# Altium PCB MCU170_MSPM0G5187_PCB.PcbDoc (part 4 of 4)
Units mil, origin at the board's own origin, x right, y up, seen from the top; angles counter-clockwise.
Board outline 2300 x 4450 mil, 4 copper layers (Top Layer, VCC Layer, GND Layer, Bottom Layer), stack 62.4 mil thick; 276 components, 190 nets, 913 pads, 323 vias.
Unrouted connection lines stored in the file: 4.
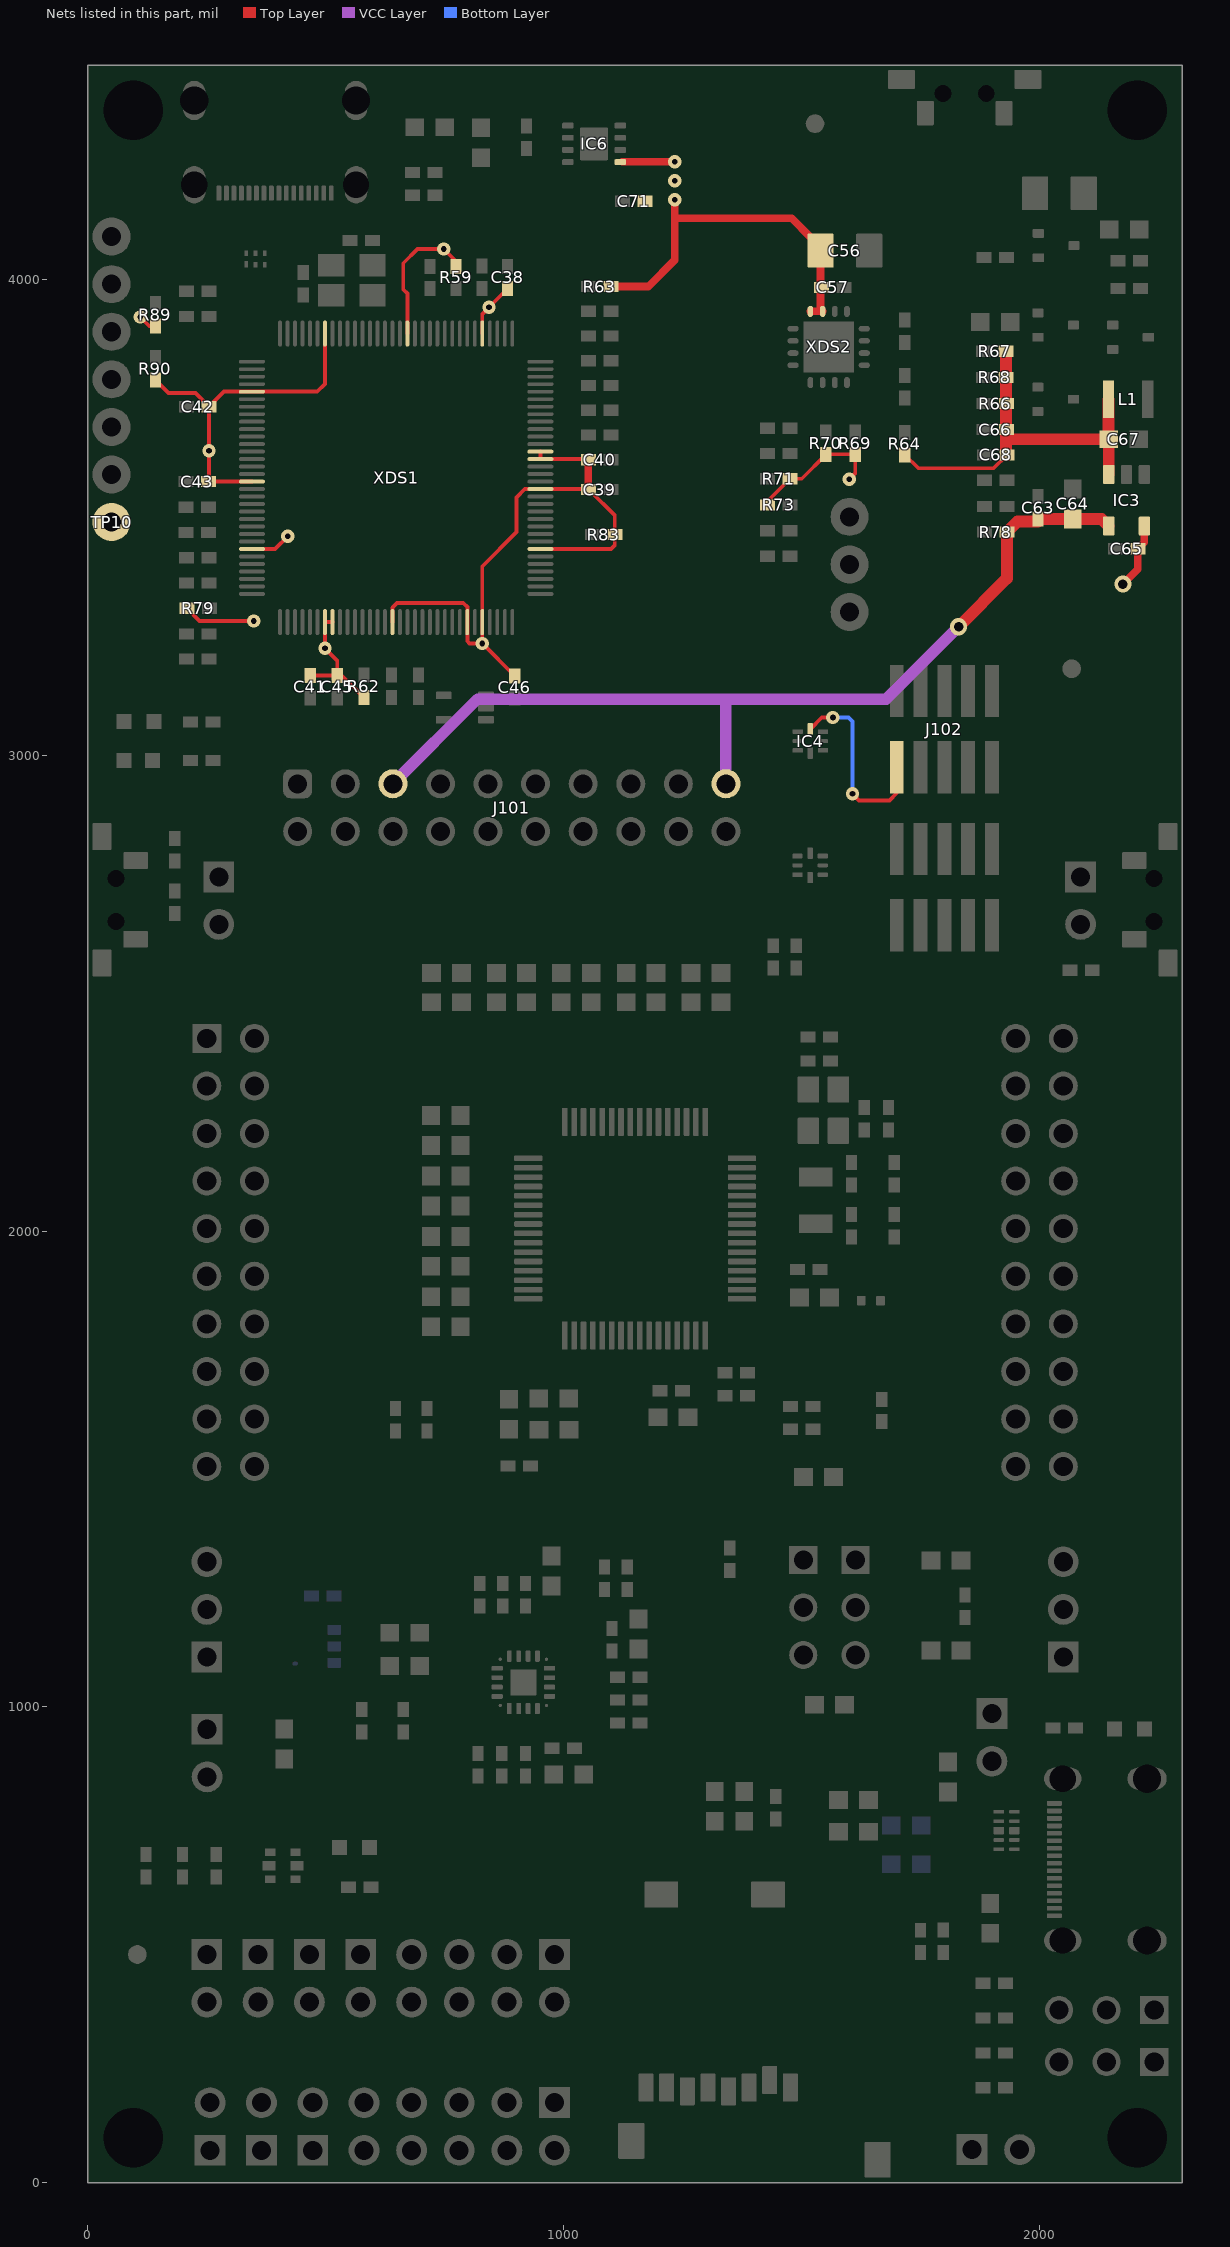
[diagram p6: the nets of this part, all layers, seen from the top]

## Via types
v1: diameter 28, hole 12, Top Layer to Bottom Layer, 291 vias
v2: diameter 19.68, hole 7.87, Top Layer to Bottom Layer, 9 vias
v3: diameter 36, hole 20, Top Layer to Bottom Layer, 8 vias
v4: diameter 24, hole 12, Top Layer to Bottom Layer, 4 vias
v5: diameter 24, hole 12, Top Layer to Bottom Layer, tented both sides, 4 vias
v6: diameter 19.68, hole 7.87, Top Layer to Bottom Layer, tented both sides, 4 vias
v7: diameter 28, hole 12, Top Layer to Bottom Layer, tented both sides, 2 vias
v8: diameter 39.37, hole 39.37, Top Layer to Bottom Layer, 1 vias

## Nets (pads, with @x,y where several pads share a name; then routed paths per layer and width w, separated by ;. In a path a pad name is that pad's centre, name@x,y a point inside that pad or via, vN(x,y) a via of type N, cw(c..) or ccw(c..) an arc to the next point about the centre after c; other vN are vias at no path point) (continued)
XDS_VCC: C38.1 C39.1 C40.1 C41.1 C42.1 C43.1 C45.1 C46.1 C56.1 C57.1 C65.1 C71.1 IC3.5 IC4.8 IC6.1 J102.1 R59.2 R62.2 R63.2 R69.2 R70.2 R71.2 R73.2 R79.2 R83.2 R89.1 R90.1 TP10.1 XDS1.7 XDS1.8 XDS1.16 XDS1.26 XDS1.28 XDS1.39 XDS1.47 XDS1.51 XDS1.52 XDS1.69 XDS1.79 XDS1.90 XDS1.101 XDS1.113 XDS1.122 XDS2.15 XDS2.16 | length 4812.5
  Top Layer w8: v1(110.33,3921) 129.2,3902.13 R89.1@142,3902.13 ; R90.1@142,3788.76 169.76,3761 226.23,3761 C42.1@254.62,3732.61 ; R79.2@208,3309 235,3282 v1(349,3282) ; C43.1@253.62,3575 C43.1@253.75,3575.13 ; XDS1.122@344.85,3433.39 393.39,3433.39 v1(420,3460) ; XDS1.113@344.85,3575.13 C43.1@253.75,3575.13 ; C41.1@467.5,3167.62 C45.1@524,3167.62 ; XDS1.90@498.39,3886.15 498.39,3780.3 482.19,3764.1 XDS1.101@344.85,3764.1 286.12,3764.1 C42.1@254.62,3732.61 ; XDS1.8@514.14,3279.85 XDS1.7@498.39,3279.85 v1(498.39,3224.61) 524,3199 C45.1@524,3167.62 ; R62.2@580.4,3121.01 533.79,3167.62 C45.1@524,3167.62 ; XDS1.16@640.13,3279.85 640.13,3310.13 650,3320 789,3320 797.61,3311.39 XDS1.26@797.61,3279.85 797.61,3239.39 802.1,3234.9 v1(829.1,3234.9) ; XDS1.79@671.62,3886.15 671.62,3970.06 663,3978.68 663,4034.06 692.94,4064 v1(748,4064) 774,4038 R59.2@774,4027.62 ; XDS1.69@829.1,3886.15 829.1,3927.48 v1(843,3941.38) C38.1@882,3980.38 ; C46.1@897,3167 v1(829.1,3234.9) ; XDS1.39@951.15,3433.39 1099.47,3433.39 1107.55,3441.48 R83.2@1107.55,3463.63 1107.55,3503.73 C39.1@1055.98,3555.31 ; XDS1.52@951.15,3638.12 XDS1.51@951.15,3622.37 C40.1@1051.04,3622.37 ; C39.1@1051.04,3559.38 XDS1.47@951.15,3559.38 918.38,3559.38 901,3542 901,3469.21 829.1,3397.31 XDS1.28@829.1,3279.85 v1(829.1,3234.9) ; C39.1@1052.04,3563 C39.1@1055.98,3563 ; R73.2@1428.38,3526 1428.38,3533.76 R71.2@1475.62,3581 1500.27,3581 R70.2@1551,3631.73 1551.65,3632.38 R69.2@1613,3632.38 1613,3593 v1(1600,3580) ; IC4.8@1518.56,3055.47 1542.24,3079.15 v1(1565.85,3079.15) ; v1(1607,2919) 1621,2905 1684.72,2905 1700,2920.28 J102.1@1700,2974.88 ; C43.1@253.75,3575.13 254.62,3576 v1(254.62,3640) C42.1@254.62,3732.61
  Top Layer w16: C39.1@1052.04,3563 C40.1@1052.04,3621 ; R63.2@1099.29,3985 1177.45,3985 1233.24,4040.79 1233.24,4122.95 v1(1233.24,4167.54) ; IC6.1@1122.76,4247.54 v1(1233.24,4247.54) ; 1233.24,4128.48 1479.37,4128.48 1519.84,4088.01 1520.28,4088.01 1539.84,4068.45 1539.84,3983 1539.84,3937.17 XDS2.15@1544.2,3932.8 XDS2.16@1518.61,3932.8 ; v3(2175.23,3359.67) 2206.62,3391.06 C65.1@2206.62,3434 2220.4,3447.78 IC3.5@2220.4,3481.73
  Bottom Layer w8: v1(1565.85,3079.15) 1598.85,3079.15 1607,3071 v1(1607,2919)
  other v1: 1233.24,4207.54
XDS_VCCOUT: C66.1 C67.2 C68.1 IC3.3 L1.2 R64.2 R66.2 R67.2 R68.2 | length 830.6
  Top Layer w8: R64.2@1717,3631.38 1745.38,3603 1903.62,3603 C68.1@1931.62,3631
  Top Layer w25: R67.2@1930,3849.2 R68.2@1930,3794 1930,3663.85 ; C68.1@1931.62,3631 1930,3632.62 1930,3663.85 ; L1.2@2145.06,3748 2145.06,3664.44 C67.2@2145.5,3664 ; IC3.3@2145.6,3590 2145.5,3590.09 C67.2@2145.5,3664 ; 1930,3663.85 1930.15,3664 C67.2@2145.5,3664
XDS_VCCTARGET: C63.1 C64.1 IC3.4 J101.5 J101.19 R78.2 | length 1979.4
  Top Layer w25: v3(1830,3270) 1931.62,3371.62 R78.2@1931.62,3469 1953.44,3490.81 1997,3490.81 C63.1@1997,3496.38 2130.95,3496.38 IC3.4@2145.6,3481.73
  VCC Layer w24: J101.5@641.04,2940 819.04,3118 1341.04,3118 ; J101.19@1341.04,2940 1341.04,3118 ; v3(1830,3270) 1678,3118 1436.65,3118 1341.04,3118
pads on no net: FID1.1 FID2.1 FID3.1 IC2.2 IC2.4 IC2.5 IC5.1 IC5.2 IC6.2 IC6.3 IC6.6 IC6.7 J16.1 J16.8 J103.6 J103.8 J104.A8 J104.B8 J105.A8 J105.B8 MH1.1 MH2.1 MH3.1 MH4.1 S1. S2. S3. SH-J1.0 SH-J2.0 SH-J3.0 SH-J4.0 SH-J5.0 SH-J6.0 SH-J7.0 SH-J8.0 SH-J9.0 SH-J10.0 SH-J11.0 SH-J12.0 SH-J13.0 SH-J14.0 SH-J15.0 SH-J16.0 SH-J17.0 SH-J18.0 SH-J19.0 SH-J20.0 SH-J21.0 SH-J22.0 SH-J23.0 U3.1 U3.3 U4.3@1947.34,740.03 U4.6 U4.7 U4.8@1914.47,740.03 XDS1.2 XDS1.12 XDS1.13 XDS1.14 XDS1.15 XDS1.18 XDS1.19 XDS1.20 XDS1.21 XDS1.22 XDS1.23 XDS1.24 XDS1.25 XDS1.29 XDS1.30 XDS1.31 XDS1.32 XDS1.41 XDS1.43 XDS1.44 XDS1.45 XDS1.46 XDS1.53 XDS1.54 XDS1.56 XDS1.57 XDS1.65 XDS1.67 XDS1.71 XDS1.72 XDS1.73 XDS1.74 XDS1.75 XDS1.76 XDS1.81 XDS1.82 XDS1.83 XDS1.84 XDS1.85 XDS1.86 XDS1.91 XDS1.92 XDS1.102 XDS1.103 XDS1.104 XDS1.105 XDS1.106 XDS1.107 XDS1.108 XDS1.109 XDS1.110 XDS1.111 XDS1.112 XDS1.116 XDS1.117 XDS1.118 XDS1.119 XDS1.121 XDS1.123 XDS1.124 XDS1.125 XDS1.126
copper on no net:
  other v8: 435.76,1127.17

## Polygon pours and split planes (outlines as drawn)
MSP_VBUS on Top Layer "TOP_LAYER_MSP_VBUS_P089" (solid, pour order 89): 1991.58,751.04 1991.58,796.99 1900,796.99 1900,751.04
XDS_VCC on Top Layer "TOP_LAYER_XDS_VCC_P082" (solid, pour order 82): 1152.72,4270.71 1263.3,4270.71 1263.3,4105.54 1152.72,4105.54
MSP_VBUS on Top Layer "TOP_LAYER_MSP_VBUS_P088" (solid, pour order 88): 2197.07,587.34 2197.08,770.54 1860.95,770.54 1860.95,587.34
+5V on Top Layer "TOP_LAYER_+5V_P099" (solid, pour order 99): 2082.59,1072.26 2082.59,1137.38 1815.52,1137.38 1815.52,1072.26
+5V on Top Layer "TOP_LAYER_+5V_P098" (solid, pour order 98): 1939.59,951.48 1939.6,1137.38 1815.52,1137.38 1815.52,951.48
SD_VDD on Top Layer "TOP_LAYER_SD_VDD_P097" (solid, remove dead copper, pour order 97): 1290.32,793.21 1498.89,793.21 1498.89,893.53 1290.32,893.53
VBUS1 on Top Layer "TOP_LAYER_VBUS1_P081" (solid, pour order 81): 303.1,4048.74 484.25,4048.73 484.25,4367.56 303.1,4367.56
3V3 on Top Layer "TOP_LAYER_3V3_P091" (solid, remove dead copper, pour order 91): 1446.37,1931.2 1446.37,1770.25 1520.73,1770.25 1520.73,1931.2
29_VUSB on Top Layer "TOP_LAYER_29_VUSB_P092" (solid, remove dead copper, pour order 92): 1233.85,1736.75 1233.85,1512.97 1299.54,1512.97 1299.54,1736.75
GND on Top Layer "TOP_LAYER_GND_P100" (solid, remove dead copper, pour order 100): 0,2885.36 2306,2885.36 2306,0 0,0
XDS_GND on Top Layer "TOP_LAYER_XDS_GND_P083" (solid, remove dead copper, pour order 83): -6,4456 2306,4456 2306,2890 -6,2890
GND on GND Layer "GND_LAYER_GND_P096" (solid, remove dead copper, pour order 96): 0,2889.64 2298.04,2889.64 2298.04,0 0,0
XDS_GND on GND Layer "GND_LAYER_XDS_GND_P084" (solid, remove dead copper, pour order 84): -6,4456 2306,4456 2306,2890 -6,2890
VBUS1 on VCC Layer "VCC_LAYER_VBUS1_P086" (solid, remove dead copper, pour order 86): 280,4367.56 280,4048.48 515,4048.48 515,4367.56
3V3 on VCC Layer "VCC_LAYER_3V3_P095" (solid, remove dead copper, pour order 95): 0,2890 2300,2890 2300,0 0,0
MSP_VBUS on VCC Layer "VCC_LAYER_MSP_VBUS_P093" (solid, pour order 93): 2188.52,589.52 2188.53,772.73 1807.97,772.73 1807.97,589.52
XDS_VCC on VCC Layer "GND_LAYER_GND_P-001" (solid, remove dead copper, pour order 87): -6,4450 2300,4450 2300,2890 -6,2890
GND on Bottom Layer "BOTTOM_LAYER_GND_P090" (solid, remove dead copper, pour order 90): 0,2885.36 2301.96,2885.36 2301.96,0 0,0
XDS_GND on Bottom Layer "BOTTOM_LAYER_XDS_GND_P085" (solid, remove dead copper, pour order 85): -6,4456 2306,4456 2306,2890 -6,2890

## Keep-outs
Keep-Out Layer:
  text ".Layer_Name" at 527,-1268.49 h30

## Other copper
Top Layer:
  pour cut-out: 2054.2,625.96 2054.2,607.85 1973.55,607.85 1973.55,625.96
  pour cut-out: 1602.77,1834.01 1602.77,1873.14 1643.84,1873.14 1643.84,1834.01
  pour cut-out: 1643.84,1850.09 1621.72,1872.21 1677.36,1927.85 1699.48,1905.73
  pour cut-out: 1006.62,2418.91 1006.62,2448.7 1062.16,2448.7 1062.16,2418.91
  pour cut-out: 1930.57,2571.96 1930.57,2742.89 1721.74,2742.9 1721.74,2571.96
  pour cut-out: 2062.89,749.86 2062.89,733.86 1967.74,733.86 1967.74,749.86
  pour cut-out: 1322.46,1988.03 1322.46,2034.53 1358.33,2034.53 1358.33,1988.03
  pour cut-out: 1863.59,284.39 1863.59,296.77 1896.91,296.77 1896.91,284.39
  pour cut-out: 1571.6,807.81 1571.6,798.63 1448.2,798.63 1448.2,807.81
  pour cut-out: 92.29,3757.01 92.29,3763.56 162.5,3763.56 162.5,3757.01
  pour cut-out: 1632.81,2175.68 1669.62,2175.68 1669.62,2112.18 1632.81,2112.18
  pour cut-out: 1973.93,696.26 1973.93,680.26 1860.95,680.26 1860.95,696.26
  pour cut-out: 807.59,1321.24 797.5,1331.32 823.17,1356.99 833.26,1346.91
  pour cut-out: 1210,1348.42 1220.08,1358.51 1245.75,1332.84 1235.67,1322.75
  pour cut-out: 1245.75,1186.35 1229.75,1186.35 1229.75,1358.51 1245.75,1358.51
  pour cut-out: 1245.75,1358.51 1245.75,1342.51 802.42,1342.51 802.42,1358.51
  pour cut-out: 812.09,1236.12 796.09,1236.12 796.09,1358.51 812.09,1358.51
  pour cut-out: 797.51,1628.18 797.51,1640.52 926.52,1640.52 926.52,1628.18
  pour cut-out: 964.69,1543.04 964.69,1613.16 981.89,1613.16 981.89,1543.04
  pour cut-out: 795.21,1534.07 795.21,1549.53 959.27,1549.53 959.27,1534.07
  pour cut-out: 391.98,4062.32 391.98,4068.88 485.16,4068.88 485.16,4062.32
  pour cut-out: 1949.06,551.33 1949.06,527.97 1860.93,527.97 1860.93,551.33
  pour cut-out: 1865.67,366.48 1851.64,366.48 1851.64,551.28 1865.67,551.28
  pour cut-out: 991.75,1253.23 974.23,1253.23 974.23,1237.09 991.75,1237.09
  pour cut-out: 1491.99,2182.5 1491.99,2254.64 1545.49,2254.64 1545.49,2182.5
  pour cut-out: 1481.99,2435.83 1481.99,2457.64 1583.71,2457.64 1583.71,2435.83
  pour cut-out: 1218.19,1601.19 1232.22,1601.19 1232.22,1572.9 1218.19,1572.9
  pour cut-out: 1217.87,1647.79 1231.9,1647.79 1231.9,1625.57 1217.87,1625.57
  pour cut-out: 1136.51,1498.94 1136.51,1512.97 1276.11,1512.97 1276.11,1498.94
  pour cut-out: 1523.91,1770.53 1523.91,1909.48 1543.44,1909.48 1543.44,1770.53
  pour cut-out: 1667.02,1873.27 1667.02,1963.17 1705.9,1963.17 1705.9,1873.27
  pour cut-out: 1667.02,2039.54 1667.02,2076.34 1722.64,2076.34 1722.64,2039.54
  pour cut-out: 1673.19,2291.56 1654.79,2291.56 1654.79,2420.43 1673.19,2420.43
  pour cut-out: 1592.73,2380.21 1592.73,2420.43 1655.03,2420.43 1655.03,2380.21
  pour cut-out: 795.21,1534.07 795.21,1630.38 809.64,1630.38 809.64,1534.07
  pour cut-out: 1230.77,1732.08 1230.77,1768.89 1286.39,1768.89 1286.39,1732.08
  pour cut-out: 1206.56,1733.67 1206.72,1733.51 1226.43,1733.51 1226.43,1694.71 1222.91,1691.19 1198.86,1691.19
  pour cut-out: 1490.09,2047.17 1490.09,2083.98 1581.43,2083.98 1581.43,2047.17
  pour cut-out: 1930.57,2880.51 1930.57,3069 1727.58,3069 1727.58,2880.51
  text ".Layer_Name" at 527,-1268.49 h30
VCC Layer:
  text ".Layer_Name" at 527,-1268.49 h30
GND Layer:
  text ".Layer_Name" at 527,-1268.49 h30
Bottom Layer:
  pour cut-out: 548.85,1260.77 485.35,1260.77 485.35,1325.51 548.85,1325.51
  pour cut-out: 617.43,1088.43 558.39,1088.43 558.39,1119.74 617.43,1119.74
  pour cut-out: 507.61,1072.12 485.54,1050.05 473.87,1061.72 495.94,1083.79
  pour cut-out: 503.94,1168.75 503.94,1072.12 487.43,1072.12 487.43,1168.75
  pour cut-out: 485.54,1050.05 357.8,1050.05 357.8,1066.05 485.54,1066.05
  pour cut-out: 1552.81,2319.53 1552.81,2421.67 1655.71,2421.67 1655.71,2348.61 1626.63,2319.53
  text ".Layer_Name" at 527,-1268.49 h30

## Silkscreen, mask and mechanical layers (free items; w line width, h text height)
Top Overlay:
  drawing of 1922 lines, arcs and shapes, not listed
  text "MSP NRST" at 1617.89,4235.03 h40
  text "USB1" at 385.12,4107.63 h30
  text "Rev. A" at 2264.13,3068.42 h50 r90
  text "XDS110-ET Debug Probe" at 426.78,3015.68 h30
  text "Rev1.6" at 1158.45,3015.68 h30
  text "XDS110 Out" at 1650.72,2923 h30 r90
  text "LP-MSPM0G5187" at 2205.15,2920.28 h65 r90
  text "BSL" at 1261.52,2627.58 h40 r90
  text "NRST" at 970.08,2608.15 h40 r90
  text "VUSB" at 1363.44,2608.15 h40 r90
  text "XDS110 In" at 1647,2595.5 h30 r90
  text "SWDIO" at 1064.21,2592.15 h40 r90
  text "SWCLK" at 1159.62,2592.15 h40 r90
  text "RXD<<" at 765.08,2590.15 h40 r90
  text "TXD>>" at 865.08,2590.15 h40 r90
  text "(PA18)" at 212.43,2538.56 h40
  text "(PA7)" at 1860.65,2523.09 h40
  text "PB4" at 1754,2385 h60
  text "MSPM0G5187" at 994.02,2291.67 h55
  text "PA25" at 50,2285 h60
  text "PB5" at 1754,2285 h60
  text "PB26" at 2152,2285 h60
  text "PB3" at 50,2185 h60
  text "PB14" at 460,2185 h60
  text "PB0" at 1754,2185 h60
  text "PB24" at 2152,2185 h60
  text "PB2" at 50,2085 h60
  text "PB15" at 460,2085 h60
  text "PB1" at 1754,2085 h60
  text "PB23" at 2152,2085 h60
  text "PB21" at 50,1985 h60
  text "PB16" at 460,1985 h60
  text "PA28" at 1754,1985 h60
  text "NRST" at 2152,1985 h60
  text "PB22" at 50,1885 h60
  text "PA16" at 460,1885 h60
  text "PA31" at 1754,1885 h60
  text "PB17" at 2152,1885 h60
  text "PB18" at 50,1785 h60
  text "PA15" at 460,1785 h60
  text "PA10" at 1754,1785 h60
  text "PB19" at 2152,1785 h60
  text "PB25" at 50,1685 h60
  text "PA12" at 460,1685 h60
  text "PA11" at 1754,1685 h60
  text "PA30" at 2152,1685 h60
  text "PA9" at 50,1585 h60
  text "PA13" at 460,1585 h60
  text "PA0" at 1754,1585 h60
  text "PA29" at 2152,1585 h60
  text "PA8" at 50,1485 h60
  text "PA14" at 460,1485 h60
  text "PA1" at 1754,1485 h60
  text "PA22" at 2152,1485 h60
  text "PCM1809" at 1013.29,1331.99 h60
  text "3V" at 1381.47,1300.72 h60
  text "3V" at 1671.76,1300.46 h60
  text "Microphone" at 441.8,1275 h60
  text "5V" at 1376.79,1080.14 h60
  text "5V" at 1671.72,1077.85 h60
  text "PA0" at 1387.36,1004.06 h60
  text "PA1" at 1640.23,1003.4 h60
  text "5V" at 1763.28,968.15 h60
  text "VM" at 121.82,941.97 h50
  text "VBUS" at 1974.04,882.55 h60
  text "3V3" at 109.67,836.79 h50
  text "PB12" at 630.33,584.83 h48
  text "PB10" at 740.05,585.36 h48
  text "PB8" at 850,585.36 h48
  text "PB6" at 945.06,585.36 h48
  text "USB2" at 2001.8,579.54 h30 r90
  text "PB13" at 630.33,543.16 h48
  text "PB11" at 743.14,542.62 h48
  text "PB9" at 850,543.16 h48
  text "PB7" at 945.06,542.62 h48
  text "DEVICE" at 2137.8,449.11 h40
  text "J25" at 1967.29,432.47 h30
  text "24" at 2071.05,432.08 h30
  text "/" at 2051.96,428.02 h60
  text "PB13" at 129,287.84 h48
  text "PA0" at 488,287.84 h48
  text "PA17" at 248.71,287.31 h48
  text "PA24" at 368.42,287.31 h48
  text "B20" at 644.42,281.13 h50
  text "A6" at 754.29,281.13 h50
  text "A4" at 854.48,280.58 h50
  text "A27" at 944.83,280.58 h50
  text "A2" at 579,270 h48
  text "A21" at 644.42,234.72 h50
  text "A5" at 753.19,235.28 h50
  text "A3" at 854.04,235.28 h50
  text "A26" at 944.83,235.28 h50
  text "GND" at 209.53,230 h48
  text "3V3" at 333,230 h48
  text "5V" at 448.26,230 h48
  text "A23" at 554.8,227.5 h48
  text "CC" at 1975.82,164.24 h30
  text "HOST" at 2045.96,143.35 h40
  text "PLUGIN_DETECT" at 1726.93,126.7 h40
  text "PB21" at 2021.92,18.18 h60
  text ".Layer_Name" at 527,-1268.49 h30
Bottom Overlay:
  drawing of 23340 lines, arcs and shapes, not listed
  text ".Layer_Name" at 976.62,5050.85 h60
  text "PB4" at 1860,2384.3 h60
  text "PA25" at 145.94,2285.07 h60
  text "PB5" at 1860,2284.3 h60
  text "PB26" at 2278,2284.3 h60
  text "PB3" at 145.94,2185.07 h60
  text "PB14" at 580,2185.07 h60
  text "PB0" at 1860,2184.3 h60
  text "PB24" at 2278,2184.3 h60
  text "PB2" at 145.94,2085.07 h60
  text "PB15" at 580,2085.07 h60
  text "PB1" at 1860,2084.3 h60
  text "PB23" at 2278,2084.3 h60
  text "PB21" at 145.94,1985 h60
  text "PB16" at 580,1985.07 h60
  text "PA28" at 1860,1984.3 h60
  text "NRST" at 2278,1984.3 h60
  text "PB22" at 145.94,1885 h60
  text "PA16" at 580,1885.07 h60
  text "PA31" at 1860,1884.3 h60
  text "PB17" at 2278,1884.3 h60
  text "PB18" at 145.94,1785.07 h60
  text "PA15" at 580,1785.07 h60
  text "PA10" at 1860,1784.3 h60
  text "PB19" at 2278,1784.3 h60
  text "PB25" at 145.94,1685.07 h60
  text "PA12" at 580,1685.07 h60
  text "PA11" at 1860,1684.3 h60
  text "PA30" at 2278,1684.3 h60
  text "PA9" at 145.94,1585.07 h60
  text "PA13" at 580,1585.07 h60
  text "PA0" at 1860,1584.3 h60
  text "PA29" at 2278,1584.3 h60
  text "PA8" at 145.94,1485.07 h60
  text "PA14" at 580,1485.07 h60
  text "PA1" at 1860,1484.3 h60
  text "PA22" at 2278,1484.3 h60
  text "DP" at 1707,799.21 h30
  text "PULL" at 2277,626 h60
  text "DM" at 1707,586.99 h30
  text "PULLUP" at 2082.59,579 h60
  text "DOWN" at 2277,579 h60
  text "CC2" at 1971.43,342.73 h60
  text "CC1" at 1972.43,234.73 h60
  text ".Layer_Name" at 527,-1268.49 h30
Top Paste:
  text ".Layer_Name" at 527,-1268.49 h30
Bottom Paste:
  text ".Layer_Name" at 527,-1268.49 h30
Top Solder:
  text ".Layer_Name" at 527,-1268.49 h30
  text ".Layer_Name" at 527,-1268.49 h30
Bottom Solder:
  text ".Layer_Name" at 527,-1268.49 h30
Drill Guide:
  text ".Layer_Name" at 527,-1268.49 h30
M1 Board Outline:
  the board outline again, w1
  text ".Layer_Name" at 527,-1268.49 h30
M2 Board Dimensions:
  rectangle: 75,-810 450,-685
  rectangle: -50,-685 75,-560
  lines w7: -50,-685 950,-685 ; 75,-810 75,-560 ; 200,-810 200,-560 ; 450,-810 450,-560 ; 700,-810 700,-560 ; -50,-810 -50,-560 950,-560 950,-810 -50,-810
  text ".Layer_Name" at 527,-1268.49 h30
M3 3D STEP Top:
  text ".Layer_Name" at 527,-1268.49 h30
M4 3D STEP Bottom:
  text ".Layer_Name" at 527,-1268.49 h30
M5 Assembly Top:
  circle w6: c1382.04,2127 r5.83
  lines w10: -342,-1340.17 6258,-1340.17 ; -342,-1136.83 6260,-1136.83 ; -342,-933.5 -342,-1543.5 3663,-1543.5 6260,-1543.5 6260,-933.5 -341.5,-933.5 -341.5,-1543.5 1234,-1543.5 ; 2123,-1543.5 2123,-933.5 ; 3390,-1136.83 3390,-933.5 ; 4230,-1136.83 4230,-933.5 ; 4852,-1550 4852,-1347.17
  text "COMPONENTS MARKED 'DNP' SHOULD NOT BE POPULATED." at 1103.5,-728.5 h30
  text "ASSEMBLY VARIANT:" at 1103,-844 h30
  text ".VariantName" at 2139,-844 h30
  text "PCB VIEWED FROM TOP SIDE" at -278.5,-1065.67 h30
  text "BOARD #:" at 2198,-1065.67 h30
  text ".PRJ_Number" at 2743.5,-1065.67 h30
  text "REV:" at 3588,-1065.67 h30
  text ".PCB_Rev" at 3879.5,-1065.67 h30
  text "SVN REV:" at 4426,-1065.67 h30
  text ".VersionControl_RevNumber" at 4932,-1065.67 h30
  text "TID #:" at 2198,-1269 h30
  text ".TID" at 2743.5,-1269 h30
  text "PLOT NAME =" at -278.5,-1474.34 h30
  text ".plot_File_Name" at 527,-1474.34 h30
  text "GENERATED    :" at 2200,-1474.34 h30
  text ".Print_Date" at 3069.5,-1474.34 h30
  text ".Print_Time" at 3798.5,-1474.34 h30
  text "TEXAS INSTRUMENTS" at 5063,-1474.34 h30
M6 Assembly Bottom:
  lines w10: -342.5,-1137.33 6259.5,-1137.33 ; -340.5,-1340.67 6259.5,-1340.67 ; 1065.5,-1550.5 1065.5,-1347.67 ; 1687.5,-1137.33 1687.5,-934 ; 2527.5,-1137.33 2527.5,-934 ; 3794.5,-1544 3794.5,-934 ; 4683.5,-1544 6259,-1544 6259,-934 -342.5,-934 -342.5,-1544 2254.5,-1544 6259.5,-1544 6259.5,-934
  text "COMPONENTS MARKED 'DNP' SHOULD NOT BE POPULATED." at 6052,-728 h30
  text ".VariantName" at 5008,-844 h30
  text "ASSEMBLY VARIANT:" at 6047,-844 h30
  text ".VersionControl_RevNumber" at 985.5,-1066.17 h30
  text "SVN REV:" at 1491.5,-1066.17 h30
  text ".PCB_Rev" at 2038,-1066.17 h30
  text "REV:" at 2329.5,-1066.17 h30
  text ".PRJ_Number" at 3174,-1066.17 h30
  text "BOARD #:" at 3719.5,-1066.17 h30
  text "PCB VIEWED FROM BOTTOM SIDE" at 6196,-1066.17 h30
  text ".TID" at 3174,-1269.5 h30
  text "TID #:" at 3719.5,-1269.5 h30
  text "TEXAS INSTRUMENTS" at 854.5,-1474.84 h30
  text ".Print_Time" at 2119,-1474.84 h30
  text ".Print_Date" at 2848,-1474.84 h30
  text "GENERATED    :" at 3717.5,-1474.84 h30
  text ".plot_File_Name" at 5390.5,-1474.84 h30
  text "PLOT NAME =" at 6196,-1474.84 h30
M9 Title Sheet:
  drawing of 57 lines, arcs and shapes, not listed
  text "1" at 689.84,7626.5 h30
  text "2" at 3185.5,7626.5 h30
  text "3" at 5674.84,7626.5 h30
  text "4" at 8181.51,7626.5 h30
  text "5" at 10680.5,7626.5 h30
  text "6" at 13185.5,7626.5 h30
  text "A" at -466.5,6483.5 h30
  text "A" at 14333.5,6483.5 h30
  text "B" at -466.5,4103.5 h30
  text "B" at 14333.5,4103.5 h30
  text "C" at -466.5,1728.5 h30
  text "C" at 14333.5,1728.5 h30
  text "PROJECT TITLE:" at 11293.5,-132.5 h30
  text ".PRJ_Title" at 11343.5,-265.83 h30
  text "DESIGNED FOR:" at 11293.5,-433.5 h30
  text ".PRJ_Customer" at 11343.5,-573.5 h30
  text "D" at -466.5,-641.5 h30
  text "D" at 14333.5,-641.5 h30
  text "FILE NAME:" at 11293.5,-733.5 h30
  text ".PCB_File_Name_No_Path" at 11343.5,-853.5 h30
  text "Texas Instruments (TI) and/or its licensors do not warrant the accuracy or completeness of this specification" at 6324,-1015.34 h30
  text "ENGINEER:" at 11293.5,-1023.5 h30
  text "LAYOUT BY:" at 12798.5,-1023.5 h30
  text "or any information contained therein. TI and/or its licensors do not warrant that this design will meet" at 6279.01,-1128 h30
  text ".PRJ_Engineer" at 11343.5,-1178.49 h30
  text ".PCB_Layout" at 12849,-1178.49 h30
  text "the specifications, will be suitable for your application or fit for any particular purpose, or will operate in" at 6279.01,-1240.67 h30
  text ".Layer_Name" at 527,-1268.49 h30
  text "ALTIUM DESIGNER VERSION:" at 12798.5,-1333.5 h30
  text "an implementation. TI and/or its licensors do not warrant that the design is production worthy. You should" at 6279.01,-1353.33 h30
  text "completely validate and test your design implementation to confirm the system functionality for your application." at 6324,-1466 h30
  text ".print_Scale" at 11343.5,-1466.83 h30
  text ".Application_BuildNumber" at 12849,-1466.83 h30
  text "1" at 689.84,-1673.5 h30
  text "2" at 3185.5,-1673.5 h30
  text "3" at 5674.84,-1673.5 h30
  text "4" at 8181.51,-1673.5 h30
  text "5" at 10680.5,-1673.5 h30
  text "6" at 13185.5,-1673.5 h30
M10 Fab Notes:
  drawing of 173 lines, arcs and shapes, not listed
  text "DESIGN INFORMATION" at 12328.02,5791 h30
  text "MIN. TRACK WIDTH:" at 11683.46,5611 h30
  text "8" at 12779.7,5611 h30
  text "MIL" at 12934.46,5611 h30
  text "MIN. CLEARANCE:" at 11683.46,5479 h30
  text "0.2" at 12719.7,5479 h30
  text "mm" at 12934.46,5479 h30
  text "MIN. VIA PAD SIZE:" at 11683.46,5347 h30
  text "24" at 12749.71,5347 h30
  text "MIL" at 12934.46,5347 h30
  text "0.05mm (2MIL)" at 12378.46,5205.29 h30
  text "MINIMUM ANNULAR RING" at 11354.23,5201 h30
  text "EXTERNAL" at 13086.46,5201 h30
  text "PER" at 11554.23,5083 h30
  text "IPC-D-275 CLASS 2 LEVEL C" at 11774.23,5083 h30
  text "MIL, HOLES" at 13262.46,4970.71 h30
  text "+/-" at 12870,4970 h30
  text "+/-" at 13724,4970 h30
  text "REGISTRATION TOLERANCES:" at 11354.23,4965 h30
  text "METAL" at 12554,4965 h30
  text "5" at 13130.2,4965 h30
  text "3" at 13963.2,4965 h30
  text "MIL" at 14079.46,4965 h30
  text "+/-" at 13724,4852 h30
  text "HOLE SIZE TOLERANCE (UNLESS OTHERWISE SPECIFIED):" at 11354.23,4847 h30
  text "3" at 13963.2,4847 h30
  text "MIL" at 14079.46,4847 h30
  text "MATERIAL:" at 11279.46,4637.54 h30
  text "FR-4 High Tg" at 12265.9,4497.21 h30
  text "FR-408" at 11700.46,4488.64 h30
  text "OTHER" at 13188.46,4488.64 h30
  text "X" at 12111,4485 h30
  text "62 MIL (1.6mm) +/-10%" at 12020.56,4325.92 h30
  text "THICKNESS:" at 11354.23,4321.64 h30
  text "X" at 11892.4,4321.64 h30
  text "OTHER" at 13305.46,4321.64 h30
  text "TOLERANCE:" at 11354.23,4163.64 h30
  text "X" at 12193.53,4163.64 h30
  text "ANSI IPC-6012 TYPE 3 CLASS 2" at 12380.48,4163.64 h30
  text "OTHER +/-" at 12380.46,4007.64 h30
  text "BOW & TWIST:" at 11354.23,3850.64 h30
  text "X" at 12193.53,3850.64 h30
  text "ANSI IPC-6012 TYPE 3 CLASS 2" at 12380.48,3850.64 h30
  text "OTHER +/-" at 12380.46,3692.13 h30
  text "DRILLING:" at 11279.46,3553.64 h30
  text "REFERENCE:" at 11354.23,3436.64 h30
  text "X" at 12002.46,3436.64 h30
  text "AS SHOWN" at 12189.46,3436.64 h30
  text "X" at 12903.46,3436.64 h30
  text "NC_DRILL FILES" at 13040.46,3436.64 h30
  text "PTH COPPER THICKNESS:" at 11354.23,3278.64 h30
  text "X" at 12484.46,3278.64 h30
  text "20-30 um" at 12621.46,3278.64 h30
  text "OTHER" at 13338.46,3278.64 h30
  text "BOARD FINISH:" at 11279.46,3119.64 h30
  text "SILKSCREEN:" at 11434.68,3001.64 h30
  text "X" at 12383.46,3001.64 h30
  text "TOP" at 12509.46,3001.64 h30
  text "X" at 12893.46,3001.64 h30
  text "BOTTOM" at 13020.46,3001.64 h30
  text "SILKSCREEN COLOR:" at 11434.68,2834.64 h30
  text "X" at 12382.42,2834.64 h30
  text "WHITE" at 12509.46,2834.64 h30
  text "OTHER" at 13020.46,2834.64 h30
  text "GREEN" at 12640.46,2675.44 h30
  text "X" at 13105,2675 h30
  text "OTHER" at 13258.46,2675.44 h30
  text "Red" at 13655,2675 h30
  text "SOLDER RESIST COLOR:" at 11434.68,2664.64 h30
  text "X" at 12513.42,2505.44 h30
  text "MATTE" at 12640.46,2505.44 h30
  text "SEMI-GLOSS" at 13258,2504.8 h30
  text "IMMERSION GOLD (ENIG)" at 12340.46,2316.92 h30
  text "ENEPIG" at 13678,2313.64 h30
  text "SURFACE FINISH:" at 11279.46,2312.64 h30
  text "IMM. TIN/SILVER OR EQUIV" at 11609,2155.64 h30
  text "OTHER" at 13040.46,2155.64 h30
  text "X" at 11445,2155 h30
  text "ARRAY/PANEL:" at 11279.46,1976.64 h30
  text "CUT AND TRIM PER M1 BOARD OUTLINE" at 12340.46,1972.35 h30
  text "N.C. ROUTE" at 12340.46,1820.64 h30
  text "X" at 13019.46,1820.64 h30
  text "V. SCORE" at 13206.46,1820.64 h30
  text "CERTIFICATION:" at 11279.46,1683.64 h30
  text "MATERIALS AND WORKMANSHIP FOR ALL PCBS" at 12004.46,1683.64 h30
  text "TO MEET OR EXCEED THE REQUIREMENTS OF:" at 12004.46,1585.64 h30
  text "X" at 11630.96,1449.13 h30
  text "ANSI IPC-A-600F CLASS ->" at 11769.96,1449.13 h30
  text "X" at 13409.02,1449.13 h30
  text "2" at 13527.96,1449.14 h30
  text "1" at 13212.96,1447.64 h30
  text "3" at 13881.96,1447.64 h30
  text "X" at 12445.02,1289.64 h30
  text "RoHS" at 12581.96,1289.64 h30
  text "OTHER" at 13226.36,1289.64 h30
  text "PER ORDER" at 13623.42,1289.64 h30
  text "ALL BOARDS MUST MEET OR EXCEED UL94-V0 REQUIREMENTS." at 11307,1124 h30
  text "PCB MUST BEAR THE UL94V-0 UL REGISTERED MATERIAL ID NUMBER" at 11307,1004 h30
  text "ADDITIONAL REQUIREMENTS:" at 11279.46,830.64 h30
  text "MICROSECTION:" at 11354.23,715.64 h30
  text "YES" at 12259.96,715.64 h30
  text "X" at 13585,560 h30
  text "REQUIRED" at 13121.46,559.49 h30
  text "BARE BOARD ELEC. TEST:" at 11354.23,556.64 h30
  text "NONE" at 12659.96,556.64 h30
  text "PER ORDER" at 13713.46,556.64 h30
  text ".Layer_Name" at 527,-1268.49 h30
M11 Gerber Information:
  lines w10: -342,-1340.17 6258,-1340.17 ; -342,-1136.83 6260,-1136.83 ; -342,-933.5 -342,-1543.5 3663,-1543.5 6260,-1543.5 6260,-933.5 -341.5,-933.5 -341.5,-1543.5 1234,-1543.5 ; 2123,-1543.5 2123,-933.5 ; 3390,-1136.83 3390,-933.5 ; 4230,-1136.83 4230,-933.5 ; 4852,-1550 4852,-1347.17
  text "ALL ARTWORK VIEWED FROM TOP SIDE" at -278.5,-1065.67 h30
  text "BOARD #:" at 2198,-1065.67 h30
  text ".PRJ_Number" at 2743.5,-1065.67 h30
  text "REV:" at 3588,-1065.67 h30
  text ".PCB_Rev" at 3879.5,-1065.67 h30
  text "SVN REV:" at 4426,-1065.67 h30
  text ".VersionControl_RevNumber" at 4932,-1065.67 h30
  text "LAYER NAME =" at -278.5,-1268.49 h30
  text "TID #:" at 2198,-1269 h30
  text ".TID" at 2743.5,-1269 h30
  text "PLOT NAME =" at -278.5,-1474.34 h30
  text ".plot_File_Name" at 527,-1474.34 h30
  text "GENERATED    :" at 2200,-1474.34 h30
  text ".Print_Date" at 3069.5,-1474.34 h30
  text ".Print_Time" at 3798.5,-1474.34 h30
  text "TEXAS INSTRUMENTS" at 5063,-1474.34 h30
M12 Stackup:
  drawing of 295 lines, arcs and shapes, not listed
  text "Layer" at 2632.17,3150 h30
  text "Name" at 2847.13,3150 h30
  text "Material" at 3322,3150 h30
  text "Thickness" at 3611.93,3150 h30
  text "Constant" at 3946.85,3150 h30
  text "Board Layer Stack" at 4241.78,3150 h30
  text "Top Overlay" at 2847.13,3090 h30
  text "Top Solder" at 2847.13,3030 h30
  text "SM-004" at 3322,3030 h30
  text "0.98mil" at 3611.93,3030 h30
  text "4" at 3946.85,3030 h30
  text "1" at 2632.17,2970 h30
  text "Top Layer" at 2847.13,2970 h30
  text "1.40mil" at 3611.93,2970 h30
  text "Dielectric 2" at 2847.13,2910 h30
  text "FR-4" at 3322,2910 h30
  text "8.40mil" at 3611.93,2910 h30
  text "4.2" at 3946.85,2910 h30
  text "2" at 2632.17,2850 h30
  text "VCC Layer" at 2847.13,2850 h30
  text "1.40mil" at 3611.93,2850 h30
  text "Dielectric1" at 2847.13,2790 h30
  text "FR-4" at 3322,2790 h30
  text "40.00mil" at 3611.93,2790 h30
  text "4.2" at 3946.85,2790 h30
  text "3" at 2632.17,2730 h30
  text "GND Layer" at 2847.13,2730 h30
  text "1.40mil" at 3611.93,2730 h30
  text "Dielectric 3" at 2847.13,2670 h30
  text "FR-4" at 3322,2670 h30
  text "8.40mil" at 3611.93,2670 h30
  text "4.2" at 3946.85,2670 h30
  text "4" at 2632.17,2610 h30
  text "Bottom Layer" at 2847.13,2610 h30
  text "1.40mil" at 3611.93,2610 h30
  text "Bottom Solder" at 2847.13,2550 h30
  text "SM-004" at 3322,2550 h30
  text "0.98mil" at 3611.93,2550 h30
  text "4" at 3946.85,2550 h30
  text "Bottom Overlay" at 2847.13,2490 h30
  text ".Layer_Name" at 527,-1268.49 h30
M13 Component Bodies Top:
  text ".Layer_Name" at 527,-1268.49 h30
M14 Component Bodies Bottom:
  text ".Layer_Name" at 527,-1268.49 h30
M15 Courtyards Top:
  text ".Layer_Name" at 527,-1268.49 h30
M16 Courtyards Bottom:
  text ".Layer_Name" at 527,-1268.49 h30
Drill Drawing:
  circle w10: c2638.27,4188.56 r10
  circle w10: c2638.27,4188.56 r16.67
  circle w10: c2638.27,3963.56 r16.67
  lines w10: 2621.6,3646.89 2654.94,3646.89 2654.94,3680.22 2621.6,3680.22 2621.6,3646.89 ; 2621.6,3730.22 2629.94,3730.22 2638.27,3721.89 2646.6,3730.22 2654.94,3730.22 2646.6,3738.56 2654.94,3746.89 2646.6,3746.89 2638.27,3755.22 2629.94,3746.89 2621.6,3746.89 2629.94,3738.56 2621.6,3730.22 ; 2621.6,3796.89 2638.27,3805.22 2654.94,3796.89 2646.6,3813.56 2654.94,3830.22 2638.27,3821.89 2621.6,3830.22 2629.94,3813.56 2621.6,3796.89 ; 2621.6,3905.22 2654.94,3905.22 2638.27,3871.89 2621.6,3905.22 ; 2621.6,4055.22 2654.94,4055.22 2638.27,4021.89 2621.6,4055.22 ; 2621.6,4105.22 2629.94,4105.22 2638.27,4096.89 2646.6,4105.22 2654.94,4105.22 2646.6,4113.56 2654.94,4121.89 2646.6,4121.89 2638.27,4130.22 2629.94,4121.89 2621.6,4121.89 2629.94,4113.56 2621.6,4105.22 ; 2621.6,4246.89 2621.6,4255.22 2629.94,4263.56 2621.6,4271.89 2621.6,4280.22 2629.94,4280.22 2638.27,4271.89 2646.6,4280.22 2654.94,4280.22 2654.94,4271.89 2646.6,4263.56 2654.94,4255.22 2654.94,4246.89 2646.6,4246.89 2638.27,4255.22 2629.94,4246.89 2621.6,4246.89 ; 2621.6,4321.89 2654.94,4321.89 2654.94,4355.22 2621.6,4355.22 2621.6,4321.89 ; 2628.27,4048.56 2648.27,4048.56 2638.27,4028.56 2628.27,4048.56 ; 2628.27,4108.56 2633.27,4108.56 2638.27,4103.56 2643.27,4108.56 2648.27,4108.56 2643.27,4113.56 2648.27,4118.56 2643.27,4118.56 2638.27,4123.56 2633.27,4118.56 2628.27,4118.56 2633.27,4113.56 2628.27,4108.56 ; 2628.27,4253.56 2628.27,4258.56 2633.27,4263.56 2628.27,4268.56 2628.27,4273.56 2633.27,4273.56 2638.27,4268.56 2643.27,4273.56 2648.27,4273.56 2648.27,4268.56 2643.27,4263.56 2648.27,4258.56 2648.27,4253.56 2643.27,4253.56 2638.27,4258.56 2633.27,4253.56 2628.27,4253.56 ; 2628.27,4328.56 2648.27,4328.56 2648.27,4348.56 2628.27,4348.56 2628.27,4328.56
  lines w12: 2590.15,3624.39 6456.1,3624.39 ; 2590.15,4374.39 6456.1,4374.39 ; 2598.35,427.59 2598.35,604.75 ; 2881.58,3549.39 2881.58,4449.39 ; 3188.9,72.17 3188.9,959.08 ; 3216.5,3549.39 3216.5,4449.39 ; 3779.45,72.17 3779.45,959.08 ; 3905.3,3549.39 3905.3,4449.39 ; 4174.24,3549.39 4174.24,4449.39 ; 4370,72.17 4370,959.08 ; 4557.14,3549.39 4557.14,4449.39 ; 4960.55,72.17 4960.55,959.08 ; 5316.92,3549.39 5316.92,4449.39 ; 5678.86,72.17 5678.86,959.08 ; 5873.76,3549.39 5873.76,4449.39 ; 6141.65,72.17 2598.35,72.17 2598.35,249.34 ; 6141.65,249.34 2598.35,249.34 ; 6141.65,426.5 2598.35,426.5 2598.35,249.34 ; 6141.65,604.75 2598.35,604.75 ; 6141.65,781.92 2598.35,781.92 ; 6142.45,72.17 6142.45,959.08 ; 2598.35,604.75 2598.35,781.92 ; 2598.35,781.92 2598.35,959.08 ; 2598.35,959.08 2598.35,1226.08 6141.65,1226.08 6141.65,959.08 2598.35,959.08 ; 2590.15,3549.39 6456.1,3549.39 6456.1,4449.39 2590.15,4449.39 2590.15,3549.39
  text "Symbol" at 2635.15,4396.89 h36
  text "Quantity" at 2904.08,4396.89 h36
  text "Finished Hole Size" at 3239,4396.89 h36
  text "Plated" at 3927.8,4396.89 h36
  text "Hole Type" at 4196.74,4396.89 h36
  text "Drill Layer Pair" at 4579.64,4396.89 h36
  text "Hole Tolerance" at 5339.42,4396.89 h36
  text "Hole Length" at 5896.26,4396.89 h36
  text "6" at 2904.08,4321.89 h30
  text "35.43mil (0.900mm)" at 3239,4321.89 h30
  text "NPTH" at 3927.8,4321.89 h30
  text "Round" at 4196.74,4321.89 h30
  text "Top Layer - Bottom Layer" at 4579.64,4321.89 h30
  text "-" at 5896.26,4321.89 h30
  text "4" at 2904.08,4246.89 h30
  text "125.00mil (3.175mm)" at 3239,4246.89 h30
  text "NPTH" at 3927.8,4246.89 h30
  text "Round" at 4196.74,4246.89 h30
  text "Top Layer - Bottom Layer" at 4579.64,4246.89 h30
  text "-" at 5896.26,4246.89 h30
  text "13" at 2904.08,4171.89 h30
  text "7.87mil (0.200mm)" at 3239,4171.89 h30
  text "PTH" at 3927.8,4171.89 h30
  text "Round" at 4196.74,4171.89 h30
  text "Top Layer - Bottom Layer" at 4579.64,4171.89 h30
  text "-" at 5896.26,4171.89 h30
  text "301" at 2904.08,4096.89 h30
  text "12.00mil (0.305mm)" at 3239,4096.89 h30
  text "PTH" at 3927.8,4096.89 h30
  text "Round" at 4196.74,4096.89 h30
  text "Top Layer - Bottom Layer" at 4579.64,4096.89 h30
  text "-" at 5896.26,4096.89 h30
  text "8" at 2904.08,4021.89 h30
  text "20.00mil (0.508mm)" at 3239,4021.89 h30
  text "PTH" at 3927.8,4021.89 h30
  text "Round" at 4196.74,4021.89 h30
  text "Top Layer - Bottom Layer" at 4579.64,4021.89 h30
  text "-" at 5896.26,4021.89 h30
  text "1" at 2904.08,3946.89 h30
  text "39.37mil (1.000mm)" at 3239,3946.89 h30
  text "PTH" at 3927.8,3946.89 h30
  text "Round" at 4196.74,3946.89 h30
  text "Top Layer - Bottom Layer" at 4579.64,3946.89 h30
  text "-" at 5896.26,3946.89 h30
  text "90" at 2904.08,3871.89 h30
  text "40.00mil (1.016mm)" at 3239,3871.89 h30
  text "PTH" at 3927.8,3871.89 h30
  text "Round" at 4196.74,3871.89 h30
  text "Top Layer - Bottom Layer" at 4579.64,3871.89 h30
  text "-" at 5896.26,3871.89 h30
  text "40" at 2904.08,3796.89 h30
  text "40.16mil (1.020mm)" at 3239,3796.89 h30
  text "PTH" at 3927.8,3796.89 h30
  text "Round" at 4196.74,3796.89 h30
  text "Top Layer - Bottom Layer" at 4579.64,3796.89 h30
  text "-" at 5896.26,3796.89 h30
  text "4" at 2904.08,3721.89 h30
  text "55.12mil (1.400mm)" at 3239,3721.89 h30
  text "PTH" at 3927.8,3721.89 h30
  text "Slot" at 4196.74,3721.89 h30
  text "Top Layer - Bottom Layer" at 4579.64,3721.89 h30
  text "23.62mil (0.600mm)" at 5896.26,3721.89 h30
  text "4" at 2904.08,3646.89 h30
  text "59.06mil (1.500mm)" at 3239,3646.89 h30
  text "PTH" at 3927.8,3646.89 h30
  text "Slot" at 4196.74,3646.89 h30
  text "Top Layer - Bottom Layer" at 4579.64,3646.89 h30
  text "23.62mil (0.600mm)" at 5896.26,3646.89 h30
  text "471 Total" at 2904.08,3571.89 h30
  text "Slot definitions :" at 2635.15,3489.4 h30
  text "Routed Path Length" at 3165.49,3489.4 h30
  text "= Calculated from tool start centre position to tool end centre position." at 3730.82,3489.4 h30
  text "Hole Length" at 3165.49,3429.42 h30
  text "= Routed Path Length + Tool Size = Slot length as defined in the PCB layout" at 3525.89,3429.42 h30
  text "IMPEDANCE TABLE | MSPM0 USB 2.0 Full Speed" at 2681.35,962.08 h120
  text "TOL." at 5678.86,787.17 h120
  text "SIGNAL" at 2598.35,783 h120
  text "LAYER" at 3188.9,783 h120
  text "WIDTH" at 3779.45,783 h120
  text "GAP" at 4370,783 h120
  text "IMPEDANCE" at 4960.55,781.92 h120
  text "(mil)" at 3777.24,610 h120
  text "(mil)" at 4367.8,610 h120
  text "(Differential)" at 4958.35,610 h120
  text "+/- 10%" at 5678.86,433.92 h120
  text "MSP_USB" at 2598.35,428.67 h120
  text "TOP" at 3188.9,428.67 h120
  text "9.6" at 3779.45,428.67 h120
  text "6" at 4370,428.67 h120
  text "90 Ohm" at 4960.55,428.67 h120
  text "+/- 10%" at 5678.86,255.67 h120
  text "VCC" at 3188.9,250.42 h120
  text "7.4" at 3779.45,250.42 h120
  text "8" at 4370,250.42 h120
  text "90 Ohm" at 4960.55,250.42 h120
  text "+/- 10%" at 5678.86,78.5 h120
  text "BOTTOM" at 3188.9,73.26 h120
  text "11.6" at 3779.45,73.26 h120
  text "8" at 4370,73.26 h120
  text "90 Ohm" at 4960.55,73.26 h120
  text ".Layer_Name" at 527,-1268.49 h30
M17 Embedded Cavity:
  text ".Layer_Name" at 527,-1268.49 h30
M18 Embedded Assembly:
  text ".Layer_Name" at 527,-1268.49 h30
M19 Embedded Keepout:
  text ".Layer_Name" at 527,-1268.49 h30

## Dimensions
0,0 to 0,4450 on M2 Board Dimensions
0,0 to 2300,0 on M2 Board Dimensions
-50,-810 to 950,-810 on M2 Board Dimensions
